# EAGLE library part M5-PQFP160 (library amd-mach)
AMD MACH SERIES
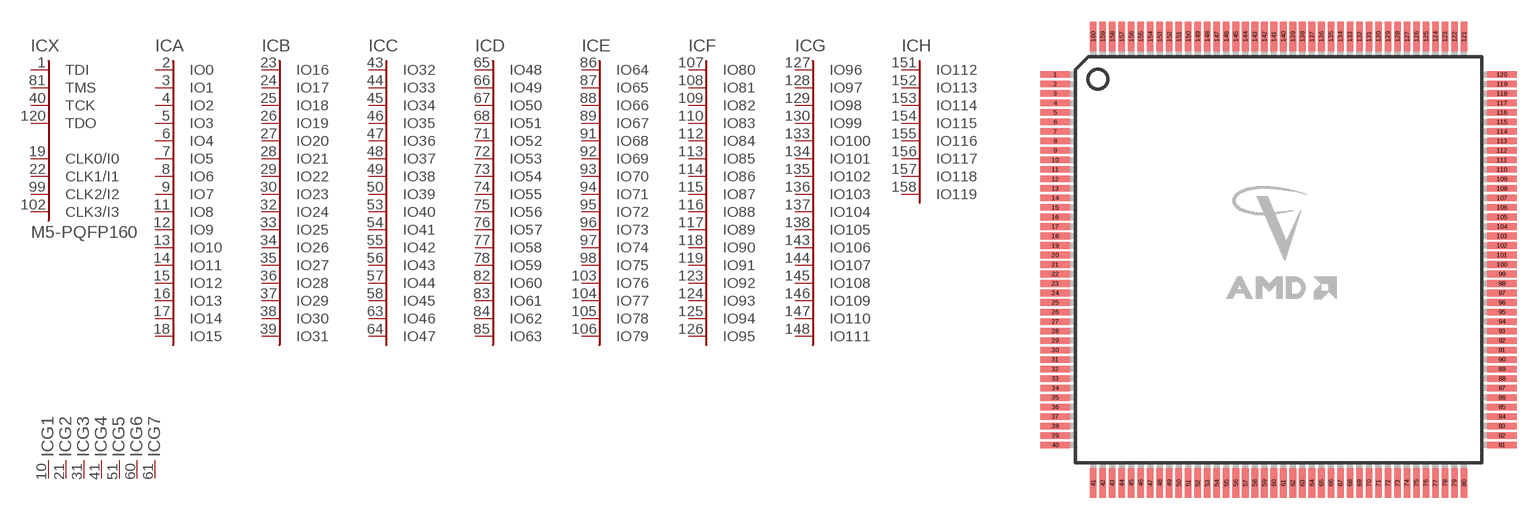
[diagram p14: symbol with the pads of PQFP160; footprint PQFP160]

Designator prefix IC; gates X=M5-CTRL A=IO15 B=IO31 C=IO47 D=IO63 E=IO79 F=IO95 G=IO111 H=IO119 G1=GND G2=GND G3=GND G4=GND G5=GND G6=GND G7=GND G8=GND G9=GND G10=GND G11=GND G12=GND G13=GND G14=GND G15=GND G16=GND G17=GND G18=GND V1=VCC V2=VCC V3=VCC V4=VCC V5=VCC V6=VCC V7=VCC V8=VCC V9=VCC V10=VCC V11=VCC V12=VCC V13=VCC V14=VCC

## M5-PQFP160 (OC_FARNELL: unknown; OC_NEWARK: unknown)  [PQFP160]
1  X:TDI  in
2  A:IO0
3  A:IO1
4  A:IO2
5  A:IO3
6  A:IO4
7  A:IO5
8  A:IO6
9  A:IO7
10  G1:GND  pwr
11  A:IO8
12  A:IO9
13  A:IO10
14  A:IO11
15  A:IO12
16  A:IO13
17  A:IO14
18  A:IO15
19  X:CLK0/I0  in
20  V1:VCC  pwr
21  G2:GND  pwr
22  X:CLK1/I1  in
23  B:IO16
24  B:IO17
25  B:IO18
26  B:IO19
27  B:IO20
28  B:IO21
29  B:IO22
30  B:IO23
31  G3:GND  pwr
32  B:IO24
33  B:IO25
34  B:IO26
35  B:IO27
36  B:IO28
37  B:IO29
38  B:IO30
39  B:IO31
40  X:TCK  in
41  G4:GND  pwr
42  V2:VCC  pwr
43  C:IO32
44  C:IO33
45  C:IO34
46  C:IO35
47  C:IO36
48  C:IO37
49  C:IO38
50  C:IO39
51  G5:GND  pwr
52  V3:VCC  pwr
53  C:IO40
54  C:IO41
55  C:IO42
56  C:IO43
57  C:IO44
58  C:IO45
59  V4:VCC  pwr
60  G6:GND  pwr
61  G7:GND  pwr
62  V5:VCC  pwr
63  C:IO46
64  C:IO47
65  D:IO48
66  D:IO49
67  D:IO50
68  D:IO51
69  V6:VCC  pwr
70  G8:GND  pwr
71  D:IO52
72  D:IO53
73  D:IO54
74  D:IO55
75  D:IO56
76  D:IO57
77  D:IO58
78  D:IO59
79  V7:VCC  pwr
80  G9:GND  pwr
81  X:TMS  in
82  D:IO60
83  D:IO61
84  D:IO62
85  D:IO63
86  E:IO64
87  E:IO65
88  E:IO66
89  E:IO67
90  G10:GND  pwr
91  E:IO68
92  E:IO69
93  E:IO70
94  E:IO71
95  E:IO72
96  E:IO73
97  E:IO74
98  E:IO75
99  X:CLK2/I2  in
100  V8:VCC  pwr
101  G11:GND  pwr
102  X:CLK3/I3  in
103  E:IO76
104  E:IO77
105  E:IO78
106  E:IO79
107  F:IO80
108  F:IO81
109  F:IO82
110  F:IO83
111  G12:GND  pwr
112  F:IO84
113  F:IO85
114  F:IO86
115  F:IO87
116  F:IO88
117  F:IO89
118  F:IO90
119  F:IO91
120  X:TDO  in
121  G13:GND  pwr
122  V9:VCC  pwr
123  F:IO92
124  F:IO93
125  F:IO94
126  F:IO95
127  G:IO96
128  G:IO97
129  G:IO98
130  G:IO99
131  G14:GND  pwr
132  V10:VCC  pwr
133  G:IO100
134  G:IO101
135  G:IO102
136  G:IO103
137  G:IO104
138  G:IO105
139  V11:VCC  pwr
140  G15:GND  pwr
141  G16:GND  pwr
142  V12:VCC  pwr
143  G:IO106
144  G:IO107
145  G:IO108
146  G:IO109
147  G:IO110
148  G:IO111
149  V13:VCC  pwr
150  G17:GND  pwr
151  H:IO112
152  H:IO113
153  H:IO114
154  H:IO115
155  H:IO116
156  H:IO117
157  H:IO118
158  H:IO119
159  V14:VCC  pwr
160  G18:GND  pwr

## Footprint PQFP160 (pad centres in mm)
PLASTIC QUAD FLAT PACK
smd 2 x 0.45: 1 -15.275,12.675; 2 -15.275,12.025; 3 -15.275,11.375; 4 -15.275,10.725; 5 -15.275,10.075; 6 -15.275,9.425; 7 -15.275,8.775; 8 -15.275,8.125; 9 -15.275,7.475; 10 -15.275,6.825; 11 -15.275,6.175; 12 -15.275,5.525; 13 -15.275,4.875; 14 -15.275,4.225; 15 -15.275,3.575; 16 -15.275,2.925; 17 -15.275,2.275; 18 -15.275,1.625; 19 -15.275,0.975; 20 -15.275,0.325; 21 -15.275,-0.325; 22 -15.275,-0.975; 23 -15.275,-1.625; 24 -15.275,-2.275; 25 -15.275,-2.925; 26 -15.275,-3.575; 27 -15.275,-4.225; 28 -15.275,-4.875; 29 -15.275,-5.525; 30 -15.275,-6.175; 31 -15.275,-6.825; 32 -15.275,-7.475; 33 -15.275,-8.125; 34 -15.275,-8.775; 35 -15.275,-9.425; 36 -15.275,-10.075; 37 -15.275,-10.725; 38 -15.275,-11.375; 39 -15.275,-12.025; 40 -15.275,-12.675; 81 15.275,-12.675; 82 15.275,-12.025; 83 15.275,-11.375; 84 15.275,-10.725; 85 15.275,-10.075; 86 15.275,-9.425; 87 15.275,-8.775; 88 15.275,-8.125; 89 15.275,-7.475; 90 15.275,-6.825; 91 15.275,-6.175; 92 15.275,-5.525; 93 15.275,-4.875; 94 15.275,-4.225; 95 15.275,-3.575; 96 15.275,-2.925; 97 15.275,-2.275; 98 15.275,-1.625; 99 15.275,-0.975; 100 15.275,-0.325; 101 15.275,0.325; 102 15.275,0.975; 103 15.275,1.625; 104 15.275,2.275; 105 15.275,2.925; 106 15.275,3.575; 107 15.275,4.225; 108 15.275,4.875; 109 15.275,5.525; 110 15.275,6.175; 111 15.275,6.825; 112 15.275,7.475; 113 15.275,8.125; 114 15.275,8.775; 115 15.275,9.425; 116 15.275,10.075; 117 15.275,10.725; 118 15.275,11.375; 119 15.275,12.025; 120 15.275,12.675
smd 0.45 x 2: 41 -12.675,-15.275; 42 -12.025,-15.275; 43 -11.375,-15.275; 44 -10.725,-15.275; 45 -10.075,-15.275; 46 -9.425,-15.275; 47 -8.775,-15.275; 48 -8.125,-15.275; 49 -7.475,-15.275; 50 -6.825,-15.275; 51 -6.175,-15.275; 52 -5.525,-15.275; 53 -4.875,-15.275; 54 -4.225,-15.275; 55 -3.575,-15.275; 56 -2.925,-15.275; 57 -2.275,-15.275; 58 -1.625,-15.275; 59 -0.975,-15.275; 60 -0.325,-15.275; 61 0.325,-15.275; 62 0.975,-15.275; 63 1.625,-15.275; 64 2.275,-15.275; 65 2.925,-15.275; 66 3.575,-15.275; 67 4.225,-15.275; 68 4.875,-15.275; 69 5.525,-15.275; 70 6.175,-15.275; 71 6.825,-15.275; 72 7.475,-15.275; 73 8.125,-15.275; 74 8.775,-15.275; 75 9.425,-15.275; 76 10.075,-15.275; 77 10.725,-15.275; 78 11.375,-15.275; 79 12.025,-15.275; 80 12.675,-15.275; 121 12.675,15.275; 122 12.025,15.275; 123 11.375,15.275; 124 10.725,15.275; 125 10.075,15.275; 126 9.425,15.275; 127 8.775,15.275; 128 8.125,15.275; 129 7.475,15.275; 130 6.825,15.275; 131 6.175,15.275; 132 5.525,15.275; 133 4.875,15.275; 134 4.225,15.275; 135 3.575,15.275; 136 2.925,15.275; 137 2.275,15.275; 138 1.625,15.275; 139 0.975,15.275; 140 0.325,15.275; 141 -0.325,15.275; 142 -0.975,15.275; 143 -1.625,15.275; 144 -2.275,15.275; 145 -2.925,15.275; 146 -3.575,15.275; 147 -4.225,15.275; 148 -4.875,15.275; 149 -5.525,15.275; 150 -6.175,15.275; 151 -6.825,15.275; 152 -7.475,15.275; 153 -8.125,15.275; 154 -8.775,15.275; 155 -9.425,15.275; 156 -10.075,15.275; 157 -10.725,15.275; 158 -11.375,15.275; 159 -12.025,15.275; 160 -12.675,15.275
